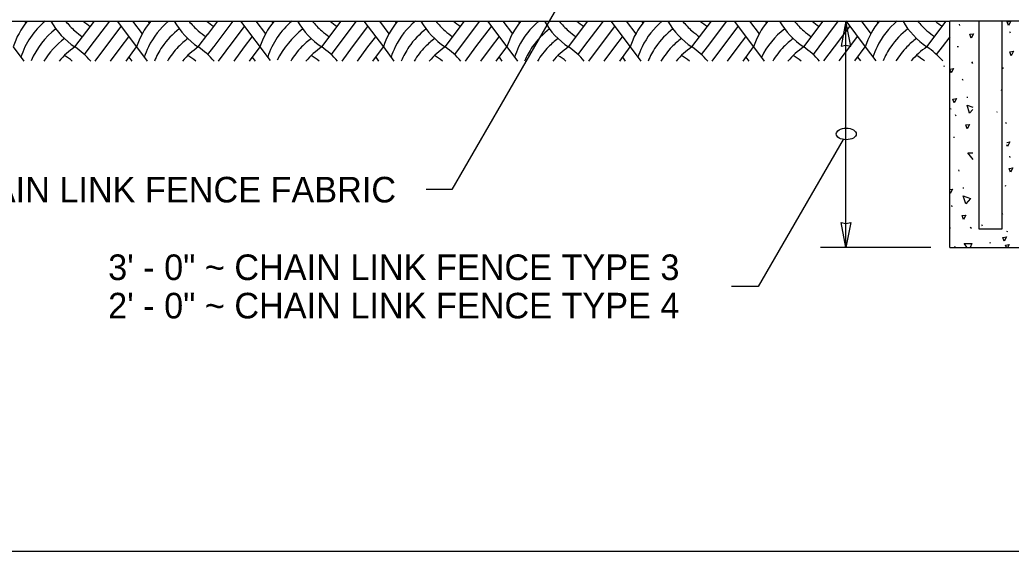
# Model space of a CAD drawing. Extents: x 99862 to 104211, y 98939 to 105076.
# Drawn here: x 100392 to 101012, y 100000 to 100332 of the extents above; entities that cross this region are included whole.
import ezdxf

# ---------------------------------------------------------------- set-up
doc = ezdxf.new("R2010")
doc.units = 0
for name, color, linetype in [('Level 1', 7, 'Continuous'), ('Level 10', 7, 'Continuous'), ('Level 15', 7, 'Continuous'), ('Level 20', 7, 'Continuous'), ('Level 6', 7, 'Continuous'), ('Level 7', 7, 'Continuous')]:
    doc.layers.add(name, color=color, linetype=linetype)

msp = doc.modelspace()

# ---------------------------------------------------------------- linework, layer by layer
at = {"layer": 'Level 1'}
msp.add_lwpolyline([(99862, 99999.5), (103151, 99999.5), (103151, 102075.5), (99862, 102075.5)], close=True, dxfattribs=at)
at = {"layer": 'Level 10'}
for p, q in [((100309.38, 100331.06), (100973.75, 100331.06)), ((100395.32, 100331.06), (100396.13, 100329.97)), ((100426.76, 100314.85), (100438.91, 100331.06)), ((100436.4, 100314.85), (100448.55, 100331.06)), ((100446.04, 100314.85), (100455.68, 100327.71)), ((100453.17, 100331.06), (100465.32, 100314.85)), ((100462.81, 100331.06), (100468.8, 100323.08)), ((100472.45, 100331.06), (100473.27, 100329.97)), ((100509.76, 100322.68), (100516.05, 100331.06)), ((100513.74, 100315.14), (100525.69, 100331.06)), ((100523.17, 100314.85), (100532.81, 100327.71)), ((100530.3, 100331.06), (100548.87, 100306.3)), ((100539.94, 100331.06), (100545.93, 100323.08)), ((100549.58, 100331.06), (100550.4, 100329.97)), ((100581.02, 100314.85), (100593.18, 100331.06)), ((100590.66, 100314.85), (100602.82, 100331.06)), ((100600.31, 100314.85), (100609.95, 100327.71)), ((100607.43, 100331.06), (100619.59, 100314.85)), ((100617.08, 100331.06), (100623.06, 100323.08)), ((100626.72, 100331.06), (100627.53, 100329.97)), ((100658.16, 100314.85), (100670.31, 100331.06)), ((100667.8, 100314.85), (100679.95, 100331.06)), ((100677.44, 100314.85), (100687.08, 100327.71)), ((100684.57, 100331.06), (100696.72, 100314.85)), ((100694.21, 100331.06), (100700.2, 100323.08)), ((100703.85, 100331.06), (100704.67, 100329.97)), ((100735.29, 100314.85), (100747.45, 100331.06)), ((100744.93, 100314.85), (100757.09, 100331.06)), ((100754.57, 100314.85), (100764.22, 100327.71)), ((100761.7, 100331.06), (100773.86, 100314.85)), ((100771.34, 100331.06), (100777.33, 100323.08)), ((100780.98, 100331.06), (100781.8, 100329.97)), ((100812.42, 100314.85), (100824.58, 100331.06)), ((100822.07, 100314.85), (100834.22, 100331.06)), ((100831.71, 100314.85), (100841.35, 100327.71)), ((100838.83, 100331.06), (100850.99, 100314.85)), ((100848.48, 100331.06), (100854.46, 100323.08)), ((100858.12, 100331.06), (100858.94, 100329.97)), ((100882.29, 100314.85), (100894.45, 100331.06)), ((100891.93, 100314.85), (100904.15, 100331.14)), ((100901.47, 100314.92), (100911.11, 100327.77)), ((100908.6, 100331.13), (100920.76, 100314.92)), ((100918.24, 100331.13), (100924.23, 100323.14)), ((100927.88, 100331.13), (100928.7, 100330.04)), ((100959.32, 100314.92), (100971.43, 100331.06)), ((100455.68, 100314.85), (100460.5, 100321.28)), ((100503.89, 100314.85), (100509.85, 100322.8)), ((100532.81, 100314.85), (100537.64, 100321.28)), ((100609.95, 100314.85), (100614.77, 100321.28)), ((100687.08, 100314.85), (100691.9, 100321.28)), ((100764.22, 100314.85), (100769.04, 100321.28)), ((100841.35, 100314.85), (100846.17, 100321.28)), ((100911.11, 100314.92), (100915.93, 100321.35)), ((100968.96, 100314.92), (100973.75, 100321.31)), ((100388.19, 100314.85), (100394.78, 100306.07)), ((100432.8, 100310.06), (100436.4, 100314.85)), ((100439.45, 100306.07), (100446.04, 100314.85)), ((100449.09, 100306.07), (100455.68, 100314.85)), ((100458.73, 100306.07), (100465.32, 100314.85)), ((100465.32, 100314.85), (100471.91, 100306.07)), ((100509.93, 100310.06), (100513.53, 100314.85)), ((100513.53, 100314.85), (100513.81, 100315.22)), ((100521.2, 100312.22), (100523.17, 100314.85)), ((100526.23, 100306.07), (100532.81, 100314.85)), ((100535.87, 100306.07), (100542.46, 100314.85)), ((100587.07, 100310.06), (100590.66, 100314.85)), ((100593.72, 100306.07), (100600.31, 100314.85)), ((100603.36, 100306.07), (100609.95, 100314.85)), ((100613, 100306.07), (100619.59, 100314.85)), ((100619.59, 100314.85), (100626.18, 100306.07)), ((100664.2, 100310.06), (100667.8, 100314.85)), ((100670.85, 100306.07), (100677.44, 100314.85)), ((100680.49, 100306.07), (100687.08, 100314.85)), ((100690.14, 100306.07), (100696.72, 100314.85)), ((100696.72, 100314.85), (100703.31, 100306.07)), ((100741.33, 100310.06), (100744.93, 100314.85)), ((100747.99, 100306.07), (100754.57, 100314.85)), ((100757.63, 100306.07), (100764.22, 100314.85)), ((100767.27, 100306.07), (100773.86, 100314.85)), ((100773.86, 100314.85), (100780.44, 100306.07)), ((100818.47, 100310.06), (100822.07, 100314.85)), ((100825.12, 100306.07), (100831.71, 100314.85)), ((100834.76, 100306.07), (100841.35, 100314.85)), ((100844.4, 100306.07), (100850.99, 100314.85)), ((100850.99, 100314.85), (100857.58, 100306.07)), ((100888.34, 100310.06), (100891.93, 100314.85)), ((100894.88, 100306.13), (100901.47, 100314.92)), ((100904.53, 100306.13), (100911.11, 100314.92)), ((100914.17, 100306.13), (100920.76, 100314.92)), ((100920.76, 100314.92), (100927.34, 100306.13)), ((100965.37, 100310.12), (100968.96, 100314.92)), ((100460.5, 100308.43), (100462.27, 100306.07)), ((100516.58, 100306.07), (100521.33, 100312.39)), ((100537.64, 100308.43), (100539.4, 100306.07)), ((100614.77, 100308.43), (100616.54, 100306.07)), ((100691.9, 100308.43), (100693.67, 100306.07)), ((100769.04, 100308.43), (100770.8, 100306.07)), ((100846.17, 100308.43), (100847.94, 100306.07)), ((100915.93, 100308.49), (100917.7, 100306.13))]:
    msp.add_line(p, q, dxfattribs=at)
for centre, radius, start, end in [((100434.69, 100300.06), 48.8, 140.56273, 162.3566), ((100439.51, 100293.64), 48.8, 129.91883, 162.35664), ((100444.33, 100287.21), 48.8, 127.1006, 157.12457), ((100453.98, 100355.36), 48.8, 209.85693, 236.09639), ((100458.8, 100361.78), 48.8, 219.01747, 228.95992), ((100463.62, 100368.21), 48.8, 229.57705, 236.09639), ((100511.83, 100300.06), 48.8, 140.56273, 162.3566), ((100516.65, 100293.64), 48.8, 129.91883, 154.2266), ((100521.47, 100287.21), 48.8, 127.1006, 145.49109), ((100531.11, 100355.36), 48.8, 209.85693, 236.09639), ((100535.93, 100361.78), 48.8, 219.01747, 228.95992), ((100540.75, 100368.21), 48.8, 229.57705, 236.09639), ((100588.96, 100300.06), 48.8, 140.56273, 162.3566), ((100593.78, 100293.64), 48.8, 129.91883, 162.3566), ((100610.21, 100275.91), 64.86, 129.25931, 151.72403), ((100608.24, 100355.36), 48.8, 209.85693, 236.09639), ((100613.06, 100361.78), 48.8, 219.01747, 228.95992), ((100617.88, 100368.21), 48.8, 229.57705, 236.09639), ((100666.09, 100300.06), 48.8, 140.56273, 162.3566), ((100670.91, 100293.64), 48.8, 129.91883, 154.2266), ((100675.74, 100287.21), 48.8, 127.1006, 145.49109), ((100685.38, 100355.36), 48.8, 209.85693, 236.09639), ((100690.2, 100361.78), 48.8, 219.01747, 228.95992), ((100695.02, 100368.21), 48.8, 229.57705, 236.09639), ((100743.23, 100300.06), 48.8, 140.56273, 162.3566), ((100748.05, 100293.64), 48.8, 129.91883, 154.2266), ((100752.87, 100287.21), 48.8, 127.1006, 145.49109), ((100762.51, 100355.36), 48.8, 209.85693, 236.09639), ((100767.33, 100361.78), 48.8, 219.01747, 228.95992), ((100772.15, 100368.21), 48.8, 229.57705, 236.09639), ((100820.36, 100300.06), 48.8, 140.56273, 162.3566), ((100825.18, 100293.64), 48.8, 129.91883, 154.2266), ((100830, 100287.21), 48.8, 127.1006, 145.49109), ((100839.64, 100355.36), 48.8, 209.85693, 236.09639), ((100844.47, 100361.78), 48.8, 219.01747, 228.95992), ((100849.29, 100368.21), 48.8, 229.57705, 236.09639), ((100897.49, 100300.06), 48.8, 140.56273, 162.3566), ((100899.87, 100287.21), 48.8, 127.1006, 154.34913), ((100909.51, 100355.36), 48.8, 209.85693, 236.09639), ((100914.33, 100361.78), 48.8, 219.01747, 228.95992), ((100919.15, 100368.21), 48.8, 229.57705, 236.09639), ((100967.26, 100300.13), 48.8, 140.56273, 162.3566), ((100972.08, 100293.7), 48.8, 129.91883, 154.2266), ((100976.9, 100287.27), 48.8, 127.1006, 145.49109), ((100986.54, 100355.42), 48.8, 209.85693, 236.09639), ((100991.36, 100361.85), 48.8, 219.01747, 228.95992), ((100996.18, 100368.28), 48.8, 229.57705, 236.09639), ((100449.16, 100280.78), 48.8, 126.33095, 148.78462), ((100458.8, 100361.78), 48.8, 228.95986, 236.09639), ((100526.29, 100280.78), 48.8, 126.331, 135.71278), ((100535.93, 100361.78), 48.8, 228.95986, 236.09639), ((100603.42, 100280.78), 48.8, 126.331, 135.71278), ((100613.06, 100361.78), 48.8, 228.95986, 236.09639), ((100680.56, 100280.78), 48.8, 126.331, 135.71278), ((100690.2, 100361.78), 48.8, 228.95986, 236.09639), ((100757.69, 100280.78), 48.8, 126.331, 135.71278), ((100767.33, 100361.78), 48.8, 228.95986, 236.09639), ((100834.82, 100280.78), 48.8, 126.331, 135.71278), ((100844.46, 100361.78), 48.8, 228.95986, 236.09639), ((100904.69, 100280.78), 48.8, 126.331, 135.71278), ((100914.33, 100361.78), 48.8, 228.95986, 236.09639), ((100981.72, 100280.84), 48.8, 126.331, 135.71278), ((100991.36, 100361.85), 48.8, 228.95986, 236.09639), ((100453.98, 100274.35), 48.8, 123.90361, 139.46006), ((100399.54, 100274.35), 48.8, 40.53994, 56.09634), ((100516.65, 100293.64), 48.8, 154.22654, 162.3566), ((100521.47, 100287.21), 48.8, 145.49102, 157.26091), ((100526.29, 100280.78), 48.8, 135.71269, 148.78462), ((100531.11, 100274.35), 48.8, 123.90361, 139.46006), ((100476.67, 100274.35), 48.8, 40.53994, 56.09634), ((100603.42, 100280.78), 48.8, 135.71269, 148.78462), ((100608.24, 100274.35), 48.8, 123.90361, 139.46006), ((100553.8, 100274.35), 48.8, 40.53994, 56.09634), ((100670.91, 100293.64), 48.8, 154.22654, 162.3566), ((100675.74, 100287.21), 48.8, 145.49102, 157.26091), ((100680.56, 100280.78), 48.8, 135.71269, 148.78462), ((100685.38, 100274.35), 48.8, 123.90361, 139.46006), ((100630.94, 100274.35), 48.8, 40.53994, 56.09634), ((100748.05, 100293.64), 48.8, 154.22654, 162.3566), ((100752.87, 100287.21), 48.8, 145.49102, 157.26091), ((100757.69, 100280.78), 48.8, 135.71269, 148.78462), ((100762.51, 100274.35), 48.8, 123.90361, 139.46006), ((100708.07, 100274.35), 48.8, 40.53994, 56.09634), ((100825.18, 100293.64), 48.8, 154.22654, 162.3566), ((100830, 100287.21), 48.8, 145.49102, 157.26091), ((100834.82, 100280.78), 48.8, 135.71269, 148.78462), ((100839.64, 100274.35), 48.8, 123.90361, 139.46006), ((100785.2, 100274.35), 48.8, 40.53994, 56.09634), ((100904.69, 100280.78), 48.8, 135.71269, 148.78462), ((100909.51, 100274.35), 48.8, 123.90361, 139.46006), ((100855.07, 100274.35), 48.8, 40.53994, 56.09634), ((100972.08, 100293.7), 48.8, 154.22654, 162.3566), ((100976.9, 100287.27), 48.8, 145.49102, 157.26091), ((100981.72, 100280.84), 48.8, 135.71269, 148.78462), ((100986.54, 100274.42), 48.8, 123.90361, 139.46006), ((100932.1, 100274.42), 48.8, 40.53994, 56.09634), ((100394.72, 100267.92), 48.8, 51.41643, 58.54646), ((100471.85, 100267.92), 48.8, 51.41643, 58.54646), ((100548.98, 100267.92), 48.8, 51.41643, 58.54646), ((100626.12, 100267.92), 48.8, 51.41643, 58.54646), ((100703.25, 100267.92), 48.8, 51.41643, 58.54646), ((100780.38, 100267.92), 48.8, 51.41643, 58.54646), ((100850.25, 100267.92), 48.8, 51.41643, 58.54646), ((100927.28, 100267.99), 48.8, 51.41643, 58.54646)]:
    msp.add_arc(centre, radius, start, end, dxfattribs=at)
at = {"layer": 'Level 15'}
for p, q in [((100772.83, 100417.01), (100662.33, 100225.63)), ((100908.71, 100189.38), (100908.71, 100331.06)), ((100907, 100257.03), (100853.92, 100165.09)), ((100662.33, 100225.63), (100646.33, 100225.63)), ((100961.71, 100189.38), (100892.71, 100189.38)), ((100853.92, 100165.09), (100837.19, 100165.09))]:
    msp.add_line(p, q, dxfattribs=at)
for points in [[(100908.71, 100331.06), (100905.62, 100315.34), (100908.71, 100316.06), (100911.79, 100315.34)], [(100908.71, 100189.38), (100905.62, 100205.1), (100908.71, 100204.37), (100911.79, 100205.1)]]:
    msp.add_lwpolyline(points, close=True, dxfattribs=at)
msp.add_ellipse((100908.89, 100260.48), major_axis=(-6.27, 0), ratio=0.57735, dxfattribs=at)
at = {"layer": 'Level 6'}
for p, q in [((100973.71, 100189.38), (100973.71, 100331.06)), ((101023.86, 100331.06), (100973.71, 100331.06)), ((100979.94, 100328.26), (100979.61, 100329.11)), ((101011.46, 100323.43), (101011.13, 100324.28)), ((100978.3, 100315.2), (100978.95, 100315.07)), ((101007.09, 100301.1), (101006.77, 100301.95)), ((100981.91, 100293.87), (100981.58, 100294.73)), ((100984.22, 100283.53), (100984.87, 100283.4)), ((101005.45, 100288.04), (101006.11, 100287.91)), ((100973.71, 100276.36), (100974.37, 100276.23)), ((100977.54, 100271.54), (100977.21, 100272.4)), ((101009.06, 100266.71), (101008.73, 100267.57)), ((100975.9, 100258.48), (100976.55, 100258.35)), ((101011.42, 100245.78), (101011.09, 100246.63)), ((100979.51, 100237.16), (100979.18, 100238.01)), ((100981.82, 100226.82), (100982.48, 100226.69)), ((101007.99, 100228.21), (101008.65, 100228.08)), ((100975.14, 100214.83), (100974.81, 100215.68)), ((101006.66, 100210), (101006.34, 100210.85)), ((100986.43, 100202.11), (100987.08, 100201.58)), ((100994, 100202.72), (100993.67, 100203.57)), ((100973.71, 100201.73), (100974.15, 100201.64)), ((101008.98, 100199.66), (101009.63, 100199.53)), ((100977.05, 100189.38), (100976.78, 100190.08)), ((100998.47, 100192.49), (100999.13, 100192.36)), ((100973.71, 100189.38), (101023.86, 100189.38))]:
    msp.add_line(p, q, dxfattribs=at)
for points in [[(101010.27, 100328.2), (101009.41, 100330.63), (101011.71, 100330.96), (101010.27, 100328.2)], [(100986.89, 100320.38), (100986.04, 100322.81), (100988.34, 100323.14), (100986.89, 100320.38)], [(101011.99, 100309.39), (101011.14, 100311.82), (101013.44, 100312.14), (101011.99, 100309.39)], [(100970.21, 100302.52), (100970, 100303.13)], [(100973.71, 100301.08), (100975.98, 100301.4), (100974.54, 100298.64)], [(100974.54, 100298.64), (100973.71, 100300.99)], [(100988.04, 100304.52), (100987.34, 100305.45), (100988.04, 100305.44)], [(100976.26, 100279.83), (100975.41, 100282.26), (100977.71, 100282.59), (100976.26, 100279.83)], [(100985.96, 100273.41), (100984.39, 100278.53), (100988.04, 100277.13)], [(100988.04, 100275.86), (100986.03, 100273.47)], [(101003.09, 100274.23), (101003.14, 100274.24), (101003.09, 100274.15)], [(100984.49, 100263.67), (100983.64, 100266.1), (100985.94, 100266.42), (100984.49, 100263.67)], [(101009.26, 100255.17), (101011.04, 100255.43), (101009.59, 100252.67)], [(101009.59, 100252.67), (101009.26, 100253.62)], [(100988.17, 100244.46), (100984.94, 100248.73), (100988.04, 100248.68)], [(101011.65, 100236.51), (101010.8, 100238.94), (101013.09, 100239.27), (101011.65, 100236.51)], [(100973.71, 100225.64), (100975.31, 100225.87), (100973.86, 100223.12)], [(100973.86, 100223.12), (100973.71, 100223.55)], [(100983.57, 100216.69), (100981.99, 100221.81), (100986.45, 100220.11), (100983.63, 100216.76)], [(100982.09, 100206.95), (100981.24, 100209.38), (100983.54, 100209.71), (100982.09, 100206.95)], [(101007.52, 100193.36), (101006.67, 100195.79), (101008.96, 100196.11), (101007.52, 100193.36)], [(100984.54, 100189.38), (100982.54, 100192.02), (100987.31, 100191.94), (100986.37, 100189.38)], [(101008.97, 100189.38), (101008.4, 100191), (101010.69, 100191.33), (101009.67, 100189.38)]]:
    msp.add_lwpolyline(points, dxfattribs=at)
at = {"layer": 'Level 7'}
msp.add_lwpolyline([(100991.68, 100330.98), (100991.68, 100201.18), (101006.31, 100201.18), (101006.31, 100330.98)], dxfattribs=at)

# ---------------------------------------------------------------- texts
at = {"layer": 'Level 20'}
for s, p in [('CHAIN LINK FENCE FABRIC', (100344.56, 100217.63)), ('3\' - 0" ~ CHAIN LINK FENCE TYPE 3 ', (100447.55, 100169.09)), ('2\' - 0" ~ CHAIN LINK FENCE TYPE 4 ', (100447.55, 100145.09))]:
    msp.add_text(s, height=16, rotation=360, dxfattribs=at).set_placement(p)

doc.saveas('drawing.dxf')
